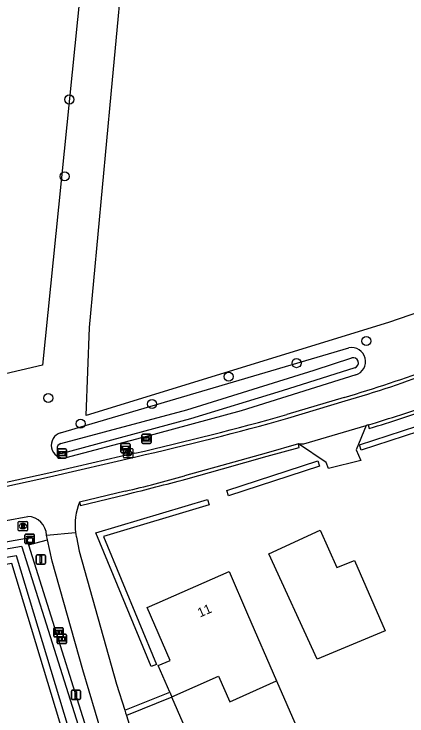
# Model space of a CAD drawing. Extents: x 162515 to 163909, y 388494 to 389773.
# Drawn here: x 163159.8 to 163202.2, y 388958.1 to 389033.6 of the extents above; entities that cross this region are included whole.
import ezdxf

# ---------------------------------------------------------------- set-up
doc = ezdxf.new("R2010")
doc.units = 0
for name, color, linetype in [('IMGEO_Berm_groen', 7, 'Continuous'), ('IMGEO_Boom', 7, 'Continuous'), ('IMGEO_Brandkraan', 7, 'Continuous'), ('IMGEO_Grasland_agrarisch', 7, 'Continuous'), ('IMGEO_Haag', 7, 'Continuous'), ('IMGEO_Informatiebord', 7, 'Continuous'), ('IMGEO_Kast', 7, 'Continuous'), ('IMGEO_Loofbos', 7, 'Continuous'), ('IMGEO_Pand', 7, 'Continuous'), ('IMGEO_Pand_nummerreeks', 7, 'Continuous'), ('IMGEO_Rijbaan_lokaal_gesloten', 7, 'Continuous'), ('IMGEO_Rijbaan_lokaal_halfverhard', 7, 'Continuous'), ('IMGEO_Rijbaan_lokaal_open', 7, 'Continuous'), ('IMGEO_Rioolput', 7, 'Continuous'), ('IMGEO_Verkeersbordpaal', 7, 'Continuous'), ('IMGEO_Verklikker', 7, 'Continuous'), ('IMGEO_Waterloop', 7, 'Continuous'), ('IMGEO_Wegwijzer', 7, 'Continuous')]:
    doc.layers.add(name, color=color, linetype=linetype)

msp = doc.modelspace()

# ---------------------------------------------------------------- linework, layer by layer
at = {"layer": 'IMGEO_Berm_groen'}
for points in [[(163125.918, 388970.212), (163125.807, 388970.958), (163161.159, 388977.199), (163161.379, 388976.501)], [(163161.379, 388976.501), (163163.438, 388977.022)], [(163161.379, 388976.501), (163169.621, 388950.367), (163177.299, 388927.553), (163179.642, 388921.834), (163181.123, 388917.659), (163182.1, 388914.357)]]:
    msp.add_lwpolyline(points, dxfattribs=at)
at = {"layer": 'IMGEO_Boom'}
for centre in [(163165.795, 389024.443), (163165.289, 389016.164), (163197.799, 388998.433), (163190.278, 388996.052), (163182.97, 388994.6), (163163.513, 388992.291), (163174.708, 388991.65), (163166.997, 388989.53)]:
    msp.add_circle(centre, 0.489, dxfattribs=at)
at = {"layer": 'IMGEO_Brandkraan'}
for p, q in [((163171.631, 388985.918), (163171.631, 388986.77)), ((163171.706, 388986.844), (163172.558, 388986.844)), ((163172.119, 388986.624), (163172.144, 388986.624)), ((163172.632, 388986.77), (163172.632, 388985.918)), ((163172.558, 388985.844), (163171.706, 388985.844)), ((163172.142, 388986.064), (163172.117, 388986.064))]:
    msp.add_line(p, q, dxfattribs=at)
for points in [[(163171.631, 388985.918), (163171.631, 388986.77)], [(163171.706, 388986.844), (163172.558, 388986.844)], [(163171.979, 388986.544), (163171.979, 388986.144), (163172.192, 388986.144)], [(163172.21, 388986.544), (163171.979, 388986.544)], [(163172.158, 388986.463), (163172.104, 388986.463), (163172.104, 388986.387)], [(163172.104, 388986.387), (163172.157, 388986.387)], [(163172.166, 388986.311), (163172.104, 388986.311), (163172.104, 388986.23)], [(163172.104, 388986.23), (163172.166, 388986.23)], [(163172.632, 388986.77), (163172.632, 388985.918)], [(163172.558, 388985.844), (163171.706, 388985.844)]]:
    msp.add_lwpolyline(points, dxfattribs=at)
for centre, radius, start, end in [((163171.708, 388986.768), 0.0765, 91.55205, 178.44795), ((163171.708, 388986.768), 0.0765, 91.55205, 178.44795), ((163172.159, 388986.425), 0.0379, 267.82845, 90.93552), ((163172.167, 388986.27), 0.0404, 269.87594, 90.50774), ((163172.214, 388986.399), 0.145, 59.4692, 91.53667), ((163172.239, 388986.446), 0.0922, 285.51372, 58.15012), ((163172.244, 388986.254), 0.105, 301.31148, 78.98903), ((163172.556, 388986.768), 0.0765, 1.55205, 88.44795), ((163172.556, 388986.768), 0.0765, 1.55205, 88.44795), ((163171.708, 388985.92), 0.0765, 181.55205, 268.44795), ((163171.708, 388985.92), 0.0765, 181.55205, 268.44795), ((163172.198, 388986.395), 0.251, 268.66757, 293.53466), ((163172.556, 388985.92), 0.0765, 271.55205, 358.44795), ((163172.556, 388985.92), 0.0765, 271.55205, 358.44795)]:
    msp.add_arc(centre, radius, start, end, dxfattribs=at)
for centre, major_axis, ratio, start_param, end_param in [((163172.118, 388986.344), (-0.387, 0.002), 0.722429, 4.712389, 7.853982), ((163172.143, 388986.344), (-0.39, 0.002), 0.717154, 1.570796, 4.712389)]:
    msp.add_ellipse(centre, major_axis=major_axis, ratio=ratio, start_param=start_param, end_param=end_param, dxfattribs=at)
at = {"layer": 'IMGEO_Grasland_agrarisch'}
msp.add_lwpolyline([(163180.426, 388914.304), (163177.974, 388921.494), (163176.525, 388925.031), (163166.878, 388950.374), (163159.581, 388974.479), (163126.1, 388968.984)], dxfattribs=at)
at = {"layer": 'IMGEO_Haag'}
for points in [[(163203.43, 388988.692), (163197.255, 388986.687), (163197.07, 388987.257), (163203.242, 388989.262)], [(163192.746, 388984.965), (163182.947, 388981.768), (163182.761, 388982.338), (163192.56, 388985.535), (163192.746, 388984.965)], [(163180.852, 388980.791), (163169.455, 388977.385), (163175.169, 388963.613), (163174.615, 388963.383), (163168.646, 388977.77), (163180.681, 388981.366), (163180.852, 388980.791)], [(163171.755, 388958.665), (163176.606, 388960.633)], [(163176.845, 388960.083), (163171.933, 388958.09)]]:
    msp.add_lwpolyline(points, dxfattribs=at)
at = {"layer": 'IMGEO_Informatiebord'}
for p, q in [((163164.129, 388966.662), (163164.129, 388967.462)), ((163164.129, 388967.462), (163164.129, 388966.662)), ((163164.229, 388967.562), (163165.019, 388967.562)), ((163165.019, 388967.562), (163164.229, 388967.562)), ((163165.119, 388967.462), (163165.119, 388966.662)), ((163165.119, 388966.662), (163165.119, 388967.462)), ((163164.486, 388965.948), (163164.486, 388966.748)), ((163164.486, 388966.748), (163164.486, 388965.948)), ((163164.586, 388966.848), (163165.376, 388966.848)), ((163165.376, 388966.848), (163164.586, 388966.848)), ((163165.476, 388966.748), (163165.476, 388965.948)), ((163165.476, 388965.948), (163165.476, 388966.748)), ((163165.019, 388966.562), (163164.229, 388966.562)), ((163164.229, 388966.562), (163165.019, 388966.562)), ((163165.376, 388965.848), (163164.586, 388965.848)), ((163164.586, 388965.848), (163165.376, 388965.848))]:
    msp.add_line(p, q, dxfattribs=at)
for points in [[(163164.23, 388967.294), (163165.018, 388967.294), (163165.018, 388966.83), (163164.23, 388966.83), (163164.23, 388967.294)], [(163164.295, 388967.229), (163164.295, 388966.895), (163164.57, 388966.895), (163164.571, 388967.108), (163164.675, 388967.109), (163164.676, 388966.895), (163164.953, 388966.895), (163164.953, 388967.229), (163164.677, 388967.229), (163164.677, 388967.149), (163164.571, 388967.149), (163164.571, 388967.229), (163164.295, 388967.229)], [(163164.587, 388966.58), (163165.375, 388966.58), (163165.375, 388966.116), (163164.587, 388966.116), (163164.587, 388966.58)], [(163164.652, 388966.515), (163164.652, 388966.181), (163164.927, 388966.181), (163164.928, 388966.394), (163165.032, 388966.395), (163165.033, 388966.181), (163165.31, 388966.181), (163165.31, 388966.515), (163165.034, 388966.515), (163165.034, 388966.435), (163164.928, 388966.435), (163164.928, 388966.515), (163164.652, 388966.515)]]:
    msp.add_lwpolyline(points, dxfattribs=at)
for centre, start, end in [((163164.229, 388967.462), 90, 180), ((163164.229, 388967.462), 90, 180), ((163165.019, 388967.462), 0, 90), ((163165.019, 388967.462), 360, 90), ((163164.229, 388966.662), 180, 270), ((163164.229, 388966.662), 180, 270), ((163164.586, 388966.748), 90, 180), ((163164.586, 388966.748), 90, 180), ((163165.019, 388966.662), 270, 0), ((163165.019, 388966.662), 270, 0), ((163165.376, 388966.748), 0, 90), ((163165.376, 388966.748), 360, 90), ((163164.586, 388965.948), 180, 270), ((163164.586, 388965.948), 180, 270), ((163165.376, 388965.948), 270, 0), ((163165.376, 388965.948), 270, 0)]:
    msp.add_arc(centre, 0.1, start, end, dxfattribs=at)
at = {"layer": 'IMGEO_Kast'}
for p, q in [((163161.008, 388976.7), (163161.008, 388977.541)), ((163161.008, 388977.541), (163161.008, 388976.7)), ((163161.083, 388977.625), (163161.924, 388977.625)), ((163161.924, 388977.625), (163161.083, 388977.625)), ((163162.008, 388977.55), (163162.008, 388976.709)), ((163162.008, 388976.709), (163162.008, 388977.55)), ((163161.933, 388976.625), (163161.092, 388976.625)), ((163161.092, 388976.625), (163161.933, 388976.625))]:
    msp.add_line(p, q, dxfattribs=at)
for points in [[(163161.203, 388977.415), (163161.803, 388977.415), (163161.803, 388977.33), (163161.203, 388977.33), (163161.203, 388977.415)], [(163161.203, 388977.24), (163161.803, 388977.24), (163161.803, 388976.751), (163161.203, 388976.751), (163161.203, 388977.24)]]:
    msp.add_lwpolyline(points, dxfattribs=at)
msp.add_circle((163161.287, 388977.089), 0.0377, dxfattribs=at)
for centre, start, end in [((163161.086, 388977.547), 92.4484, 184.28452), ((163161.086, 388977.547), 92.4484, 184.28452), ((163161.93, 388977.547), 2.4484, 94.28452), ((163161.93, 388977.547), 2.4484, 94.28452), ((163161.086, 388976.703), 182.4484, 274.28452), ((163161.086, 388976.703), 182.4484, 274.28452), ((163161.93, 388976.703), 272.4484, 4.28452), ((163161.93, 388976.703), 272.4484, 4.28452)]:
    msp.add_arc(centre, 0.0779, start, end, dxfattribs=at)
at = {"layer": 'IMGEO_Loofbos'}
for points in [[(163260.08, 389030.662), (163249.165, 389023.322), (163232.363, 389013.797), (163212.52, 389004.669), (163200.207, 389000.418), (163167.603, 388990.424), (163167.954, 388999.891), (163170.279, 389025.019), (163173.678, 389061.095), (163174.689, 389069.454), (163185.761, 389072.18), (163199.482, 389075.574), (163223.18, 389081.542), (163255.473, 389089.062)], [(163175.534, 389073.395), (163170.626, 389072.475), (163170.425, 389070.305), (163162.895, 388995.848), (163143.845, 388991.391), (163144.973, 388985.514), (163118.731, 388980.29)], [(163164.835, 388988.552), (163195.932, 388997.703)], [(163196.663, 388994.788), (163184.321, 388990.926), (163173.573, 388987.995), (163165.426, 388985.847)]]:
    msp.add_lwpolyline(points, dxfattribs=at)
for centre, radius, start, end in [((163196.213, 388996.224), 1.505, 287.39687, 100.75885), ((163165.228, 388987.221), 1.388, 106.44559, 278.20352)]:
    msp.add_arc(centre, radius, start, end, dxfattribs=at)
at = {"layer": 'IMGEO_Pand'}
for points in [[(163199.83, 388967.229), (163192.508, 388964.164), (163187.29, 388975.499), (163192.838, 388978.069), (163194.608, 388974.03), (163196.515, 388974.802), (163199.83, 388967.229)], [(163176.606, 388960.633), (163175.367, 388963.478), (163176.655, 388964.039), (163174.169, 388969.749), (163175.251, 388970.22), (163183.005, 388973.596), (163185.001, 388969.012), (163188.13, 388961.827)], [(163176.835, 388960.106), (163181.855, 388962.332), (163183.073, 388959.585), (163188.13, 388961.827)], [(163188.13, 388961.827), (163193.425, 388949.669), (163187.885, 388947.257), (163183.3, 388945.26), (163176.845, 388960.083)], [(163176.606, 388960.633), (163176.683, 388960.456), (163176.835, 388960.106)], [(163176.845, 388960.083), (163176.835, 388960.106)]]:
    msp.add_lwpolyline(points, dxfattribs=at)
at = {"layer": 'IMGEO_Rijbaan_lokaal_gesloten'}
for points in [[(163189.356, 388990.121), (163195.513, 388991.978)], [(163190.473, 388987.347), (163191.057, 388987.377), (163197.788, 388989.336)], [(163198.002, 388989.4), (163197.788, 388989.336)], [(163190.473, 388987.347), (163187.003, 388986.355), (163182.23, 388985.017), (163178.219, 388983.931)], [(163104.779, 388971.756), (163105.911, 388971.943), (163109.164, 388972.585), (163118.761, 388974.471), (163129.164, 388976.603), (163139.166, 388978.713), (163146.921, 388980.278), (163154.102, 388981.738), (163163.656, 388983.799), (163172.94, 388985.959)], [(163171.817, 388982.27), (163166.892, 388981.094)], [(163158.963, 388979.09), (163161.316, 388979.553)], [(163163.328, 388977.521), (163166.463, 388977.796)], [(163163.438, 388977.022), (163163.328, 388977.521)], [(163166.545, 388977.297), (163166.853, 388975.816), (163170.886, 388961.466), (163171.755, 388958.665)], [(163223.174, 388803.994), (163222.997, 388804.99), (163221.552, 388810.028), (163196.277, 388877.868), (163193.583, 388885.565), (163190.814, 388893.467), (163188.492, 388900.413), (163185.957, 388908.078), (163183.975, 388913.824), (163181.599, 388920.906), (163178.735, 388929.17), (163175.983, 388937.13), (163175.831, 388937.091), (163169.301, 388956.116), (163167.229, 388963.023), (163163.944, 388974.74), (163163.438, 388977.022)], [(163171.755, 388958.665), (163171.844, 388958.377), (163171.933, 388958.09)], [(163171.933, 388958.09), (163173.298, 388953.689), (163176.906, 388943.071), (163178.91, 388937.913), (163178.09, 388937.632), (163177.835, 388937.241), (163179.03, 388933.65)]]:
    msp.add_lwpolyline(points, dxfattribs=at)
for centre, radius, start, end in [((163153.605, 389134.532), 148.586, 286.38228, 290.3539), ((163153.101, 389139.283), 156.464, 286.67686, 289.36304), ((163091.865, 389340.193), 363.394, 282.8914, 285.56182), ((163147.652, 389088.576), 109.018, 282.8064, 286.283), ((163173.086, 388978.611), 6.673, 158.15969, 187.01761), ((163161.22, 388977.446), 2.109, 2.03522, 87.39806), ((163172.791, 388978.58), 6.377, 187.05944, 191.60443)]:
    msp.add_arc(centre, radius, start, end, dxfattribs=at)
at = {"layer": 'IMGEO_Rijbaan_lokaal_halfverhard'}
for points in [[(163195.397, 388992.361), (163189.249, 388990.506)], [(163198.002, 388989.4), (163198.123, 388989.019)], [(163178.332, 388983.566), (163182.303, 388984.673), (163187.117, 388986.029), (163190.578, 388986.979), (163190.473, 388987.347)], [(163172.849, 388986.349), (163163.572, 388984.19), (163154.022, 388982.13), (163146.842, 388980.67), (163139.083, 388979.104), (163129.084, 388976.995), (163118.681, 388974.863), (163105.937, 388972.354), (163104.899, 388972.165)], [(163166.892, 388981.094), (163166.978, 388980.72), (163171.912, 388981.921)]]:
    msp.add_lwpolyline(points, dxfattribs=at)
for centre, radius, start, end in [((163153.78, 389134.015), 147.641, 286.37236, 290.35997), ((163152.686, 389140.624), 158.268, 286.68362, 289.34251), ((163092.115, 389339.286), 362.053, 282.88468, 285.56234), ((163102.128, 389267.62), 294.099, 283.72615, 285.01731)]:
    msp.add_arc(centre, radius, start, end, dxfattribs=at)
at = {"layer": 'IMGEO_Rijbaan_lokaal_open'}
msp.add_lwpolyline([(163197.788, 388989.336), (163196.707, 388986.733), (163197.209, 388985.575), (163193.741, 388984.697), (163193.48, 388985.337), (163190.473, 388987.347)], dxfattribs=at)
at = {"layer": 'IMGEO_Rioolput'}
for p, q in [((163160.288, 388978.072), (163160.288, 388978.924)), ((163160.363, 388978.998), (163161.215, 388978.998)), ((163160.776, 388978.778), (163160.801, 388978.778)), ((163161.289, 388978.924), (163161.289, 388978.072)), ((163161.215, 388977.998), (163160.363, 388977.998)), ((163160.799, 388978.218), (163160.774, 388978.218))]:
    msp.add_line(p, q, dxfattribs=at)
for points in [[(163160.288, 388978.072), (163160.288, 388978.924)], [(163160.363, 388978.998), (163161.215, 388978.998)], [(163160.877, 388978.696), (163160.625, 388978.698), (163160.625, 388978.298)], [(163161.289, 388978.924), (163161.289, 388978.072)], [(163161.215, 388977.998), (163160.363, 388977.998)], [(163160.625, 388978.298), (163160.749, 388978.298), (163160.749, 388978.46), (163160.76, 388978.46)], [(163160.803, 388978.617), (163160.749, 388978.617), (163160.749, 388978.536)], [(163160.749, 388978.536), (163160.801, 388978.536)], [(163160.807, 388978.431), (163160.878, 388978.298), (163161.018, 388978.298), (163160.953, 388978.424)]]:
    msp.add_lwpolyline(points, dxfattribs=at)
for centre, radius, start, end in [((163160.365, 388978.922), 0.0765, 91.55205, 178.44795), ((163160.365, 388978.922), 0.0765, 91.55205, 178.44795), ((163160.876, 388978.586), 0.109, 350.36119, 89.41601), ((163161.213, 388978.922), 0.0765, 1.55205, 88.44795), ((163161.213, 388978.922), 0.0765, 1.55205, 88.44795), ((163160.365, 388978.074), 0.0765, 181.55205, 268.44795), ((163160.365, 388978.074), 0.0765, 181.55205, 268.44795), ((163160.759, 388978.407), 0.0533, 26.02933, 88.69889), ((163160.785, 388978.725), 0.19, 274.7715, 282.96867), ((163160.809, 388978.521), 0.0964, 77.00612, 93.18647), ((163160.823, 388978.578), 0.0378, 276.66336, 79.67722), ((163160.874, 388978.586), 0.112, 277.58423, 350.98172), ((163160.858, 388978.371), 0.108, 29.51342, 73.79051), ((163161.213, 388978.074), 0.0765, 271.55205, 358.44795), ((163161.213, 388978.074), 0.0765, 271.55205, 358.44795)]:
    msp.add_arc(centre, radius, start, end, dxfattribs=at)
for centre, major_axis, ratio, start_param, end_param in [((163160.775, 388978.498), (-0.387, 0.002), 0.722429, 4.712389, 7.853982), ((163160.8, 388978.498), (-0.39, 0.002), 0.717154, 1.570796, 4.712389)]:
    msp.add_ellipse(centre, major_axis=major_axis, ratio=ratio, start_param=start_param, end_param=end_param, dxfattribs=at)
at = {"layer": 'IMGEO_Verkeersbordpaal'}
for p, q in [((163162.22, 388974.508), (163162.22, 388975.308)), ((163162.22, 388975.308), (163162.22, 388974.508)), ((163162.32, 388975.408), (163163.11, 388975.408)), ((163163.11, 388975.408), (163162.32, 388975.408)), ((163163.21, 388975.308), (163163.21, 388974.508)), ((163163.21, 388974.508), (163163.21, 388975.308)), ((163163.11, 388974.408), (163162.32, 388974.408)), ((163162.32, 388974.408), (163163.11, 388974.408)), ((163166.006, 388959.928), (163166.006, 388960.728)), ((163166.006, 388960.728), (163166.006, 388959.928)), ((163166.106, 388960.828), (163166.896, 388960.828)), ((163166.896, 388960.828), (163166.106, 388960.828)), ((163166.996, 388960.728), (163166.996, 388959.928)), ((163166.996, 388959.928), (163166.996, 388960.728)), ((163166.896, 388959.828), (163166.106, 388959.828)), ((163166.106, 388959.828), (163166.896, 388959.828))]:
    msp.add_line(p, q, dxfattribs=at)
for points in [[(163162.64, 388975.283), (163162.79, 388975.283), (163162.79, 388974.533), (163162.64, 388974.533), (163162.64, 388975.283)], [(163166.426, 388960.703), (163166.576, 388960.703), (163166.576, 388959.953), (163166.426, 388959.953), (163166.426, 388960.703)]]:
    msp.add_lwpolyline(points, dxfattribs=at)
for centre, start, end in [((163162.32, 388975.308), 90, 180), ((163162.32, 388975.308), 90, 180), ((163163.11, 388975.308), 0, 90), ((163163.11, 388975.308), 360, 90), ((163162.32, 388974.508), 180, 270), ((163162.32, 388974.508), 180, 270), ((163163.11, 388974.508), 270, 0), ((163163.11, 388974.508), 270, 0), ((163166.106, 388960.728), 90, 180), ((163166.106, 388960.728), 90, 180), ((163166.896, 388960.728), 0, 90), ((163166.896, 388960.728), 360, 90), ((163166.106, 388959.928), 180, 270), ((163166.106, 388959.928), 180, 270), ((163166.896, 388959.928), 270, 0), ((163166.896, 388959.928), 270, 0)]:
    msp.add_arc(centre, 0.1, start, end, dxfattribs=at)
at = {"layer": 'IMGEO_Verklikker'}
for p, q in [((163171.343, 388986.496), (163171.343, 388987.296)), ((163171.343, 388987.296), (163171.343, 388986.496)), ((163171.443, 388987.396), (163172.233, 388987.396)), ((163172.233, 388987.396), (163171.443, 388987.396)), ((163172.333, 388987.296), (163172.333, 388986.496)), ((163172.333, 388986.496), (163172.333, 388987.296)), ((163164.501, 388985.91), (163164.501, 388986.71)), ((163164.501, 388986.71), (163164.501, 388985.91)), ((163164.601, 388986.81), (163165.391, 388986.81)), ((163165.391, 388986.81), (163164.601, 388986.81)), ((163165.491, 388986.71), (163165.491, 388985.91)), ((163165.491, 388985.91), (163165.491, 388986.71)), ((163172.233, 388986.396), (163171.443, 388986.396)), ((163171.443, 388986.396), (163172.233, 388986.396)), ((163165.391, 388985.81), (163164.601, 388985.81)), ((163164.601, 388985.81), (163165.391, 388985.81))]:
    msp.add_line(p, q, dxfattribs=at)
for points in [[(163171.444, 388987.128), (163172.232, 388987.128), (163172.232, 388986.664), (163171.444, 388986.664), (163171.444, 388987.128)], [(163171.509, 388987.063), (163171.509, 388986.729), (163172.167, 388986.729), (163172.167, 388987.063), (163171.509, 388987.063)], [(163164.602, 388986.542), (163165.39, 388986.542), (163165.39, 388986.078), (163164.602, 388986.078), (163164.602, 388986.542)], [(163164.667, 388986.477), (163164.667, 388986.143), (163165.325, 388986.143), (163165.325, 388986.477), (163164.667, 388986.477)]]:
    msp.add_lwpolyline(points, dxfattribs=at)
for centre, start, end in [((163171.443, 388987.296), 90, 180), ((163171.443, 388987.296), 90, 180), ((163172.233, 388987.296), 0, 90), ((163172.233, 388987.296), 360, 90), ((163164.601, 388986.71), 90, 180), ((163164.601, 388986.71), 90, 180), ((163165.391, 388986.71), 0, 90), ((163165.391, 388986.71), 360, 90), ((163171.443, 388986.496), 180, 270), ((163171.443, 388986.496), 180, 270), ((163172.233, 388986.496), 270, 0), ((163172.233, 388986.496), 270, 0), ((163164.601, 388985.91), 180, 270), ((163164.601, 388985.91), 180, 270), ((163165.391, 388985.91), 270, 0), ((163165.391, 388985.91), 270, 0)]:
    msp.add_arc(centre, 0.1, start, end, dxfattribs=at)
at = {"layer": 'IMGEO_Waterloop'}
for points in [[(163192.174, 388995.283), (163196.224, 388996.612)], [(163196.563, 388995.547), (163188.712, 388993.054), (163178.855, 388990.072), (163165.001, 388986.333)], [(163164.866, 388987.387), (163178.467, 388991.033), (163192.174, 388995.283)], [(163181.149, 388914.477), (163181.106, 388914.605), (163180.866, 388915.308), (163178.668, 388921.754), (163177.214, 388925.303), (163167.579, 388950.613), (163160.102, 388975.315), (163126.722, 388969.836), (163126.65, 388970.321), (163126.645, 388970.354), (163160.648, 388976.357), (163160.673, 388976.278), (163168.917, 388950.138), (163176.605, 388927.294), (163178.95, 388921.57), (163180.417, 388917.433), (163180.49, 388917.18)]]:
    msp.add_lwpolyline(points, dxfattribs=at)
for centre, radius, start, end in [((163196.392, 388996.079), 0.559, 287.82423, 107.48934), ((163165.009, 388986.87), 0.537, 105.47826, 269.11954)]:
    msp.add_arc(centre, radius, start, end, dxfattribs=at)
at = {"layer": 'IMGEO_Wegwijzer'}
for p, q in [((163173.61, 388987.492), (163173.61, 388988.292)), ((163173.61, 388988.292), (163173.61, 388987.492)), ((163173.71, 388988.392), (163174.5, 388988.392)), ((163174.5, 388988.392), (163173.71, 388988.392)), ((163174.6, 388988.292), (163174.6, 388987.492)), ((163174.6, 388987.492), (163174.6, 388988.292)), ((163174.5, 388987.392), (163173.71, 388987.392)), ((163173.71, 388987.392), (163174.5, 388987.392))]:
    msp.add_line(p, q, dxfattribs=at)
for points in [[(163173.711, 388988.124), (163174.499, 388988.124), (163174.499, 388987.66), (163173.711, 388987.66), (163173.711, 388988.124)], [(163173.776, 388987.976), (163173.776, 388987.892), (163173.776, 388987.808), (163174.187, 388987.808), (163174.187, 388987.725), (163174.434, 388987.892), (163174.187, 388988.059), (163174.187, 388987.976), (163173.776, 388987.976)]]:
    msp.add_lwpolyline(points, dxfattribs=at)
for centre, start, end in [((163173.71, 388988.292), 90, 180), ((163173.71, 388988.292), 90, 180), ((163174.5, 388988.292), 0, 90), ((163174.5, 388988.292), 360, 90), ((163173.71, 388987.492), 180, 270), ((163173.71, 388987.492), 180, 270), ((163174.5, 388987.492), 270, 0), ((163174.5, 388987.492), 270, 0)]:
    msp.add_arc(centre, 0.1, start, end, dxfattribs=at)

# ---------------------------------------------------------------- texts
at = {"layer": 'IMGEO_Pand_nummerreeks'}
msp.add_text('11', height=1, rotation=23.52565, dxfattribs=at).set_placement((163179.868, 388968.652))

doc.saveas('drawing.dxf')
